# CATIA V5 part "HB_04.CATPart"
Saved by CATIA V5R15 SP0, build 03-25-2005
Part number: HB_04
Material "Fire Red": density 7860 kg/m3, Young's modulus 2e+11 Pa, Poisson ratio 0.266
Bounding box of the stored display mesh (mm): x -79 to 0, y 0 to 316, z 0 to 113.2
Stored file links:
  E:\#01 CATIA Lecture Materials\#06 DMU\#11 DMU Page01 KIN EX11\HB_04.CATPart
  E:\공학과제\HB-16.CATPart
  C:\Program Files\Dassault Systemes\B20\win_b64\startup\materials\Catalog.CATMaterial
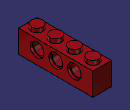
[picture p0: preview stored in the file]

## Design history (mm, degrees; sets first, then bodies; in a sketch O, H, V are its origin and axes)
Body1 (main body), material "Fire Red"
  Sketch1 on xy-plane, origin (0, 0, 0), H (1, 0, 0), V (0, 1, 0)
    circle A1 centre (-39.5, 39.5) radius 24.5
    point P1 (-39.5, 39.5)
    reference projected line E1 (0, 0) -> (0, 1264)
    reference projected line E2 (-79, 0) -> (-79, 1264)
    reference projected line E3 (-79, 0) -> (0, 0)
    radius A1 = 24.5
    distance P1 E3 = 39.5
    equidistance: E1 E2 P1
  Pad1: profile Sketch1, direction (0, 0, 1), length 113.2
  RectPattern1: of the body so far, direction 1 instances 4, spacing 79, along yz-plane
  Sketch2 on zx-plane, origin (0, 0, 0), H (-1, 0, 0), V (0, 0, 1)
    point P1 (0, 96)
    line L1 (0, 96) -> (79, 96)
    line L2 (79, 96) -> (79, 0)
    line L3 (79, 0) -> (0, 0)
    line L4 (0, 0) -> (0, 96)
    point P3 (79, 0)
    distance L2 L4 = 79
    length L2 = 96
    coincidence: P1 V, P3 H
    horizontal: L1 H, L3 H
    vertical: L2 V, L4 V
  Pad2: profile Sketch2, direction (0, 1, 0), length 316 {= RectPattern1.Nb1 * (79*1mm)}
  Plane1: type Offset, RefPlane zx-plane, Offset 79
  Sketch3 on Plane1, origin (0, 79, 0), H (-1, 0, 0), V (0, 0, 1)
    axis line L1 (95.3003, 56) -> (-23.8651, 56)
    reference projected line E1 (79, 96) -> (0, 96) from edge [start face of Pad2 | face of Pad2 from Sketch2.L1]
    point P3 (79, 56)
    line L2 (79, 56) -> (79, 85.25)
    line L3 (79, 85.25) -> (69, 85.25)
    line L4 (69, 85.25) -> (69, 80.25)
    line L5 (69, 80.25) -> (10, 80.25)
    line L6 (10, 80.25) -> (10, 85.25)
    point P8 (10, 85.25)
    line L7 (10, 85.25) -> (0, 85.25)
    point P9 (0, 85.25)
    line L8 (0, 85.25) -> (0, 56)
    point P10 (0, 56)
    reference projected line E2 (79, 0) -> (79, 96) from edge [start face of Pad2 | face of Pad2 from Sketch2.L2]
    distance L1 E1 = 40
    distance L8 L6 = 10
    distance L4 L2 = 10
    distance L5 L1 = 24.25
    distance L7 L1 = 29.25
    horizontal: L1 H, L3 H, L5 H, L7 H
    coincidence: P3 L1, P8 L3, P9 V, P10 L1, L2 E2
    vertical: L2 V, L4 V, L6 V, L8 V
  Groove1: profile Sketch3, axis Sketch3.L1, angle 360
  RectPattern2: of Groove1, direction 1 instances 3 {= RectPattern1.Nb1 - 1}, spacing 79, along edge [face of Pad2 from Sketch2.L4 | face of Pad2 from Sketch2.L1]
  Shell1: ExtOffset 0, Face face of Pad2, IntOffset 10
